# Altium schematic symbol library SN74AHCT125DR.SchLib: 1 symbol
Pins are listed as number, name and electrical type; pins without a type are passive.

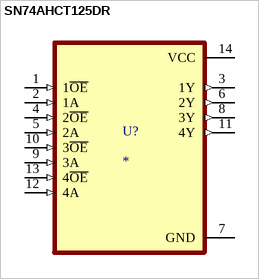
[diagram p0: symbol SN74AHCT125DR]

## SN74AHCT125DR
designator U?
4-ch, 4.5-V to 5.5-V buffers with TTL-compatible CMOS inputs and 3-state outputs; MF: Texas Instruments; MP: SN74AHCT125DR
footprint SOIC127P600X175-14N
pins: 1 1~{OE} (in), 2 1A (in), 3 1Y (out), 4 2~{OE} (in), 5 2A (in), 6 2Y (out), 7 GND (power), 8 3Y (out), 9 3A (in), 10 3~{OE} (in), 11 4Y (out), 12 4A (in), 13 4~{OE} (in), 14 VCC (power)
